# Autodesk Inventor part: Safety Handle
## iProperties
Created: 2002-02
Part Number: Safety Handle
Document SubType Name: Modeling
Designer: ***
Control State: 0
Master: False
Checked Out: False
Shininess: 77.0
Length Units: 11269
Angle Units: 11279
Time Units: 11290
Mass Units: 11283
Length Display Precision: 3
Angle Display Precision: 2
Density: 0.0
Volumn: 0.0
Area: 0.0
PropertySet Name: Model Information
Author: ***
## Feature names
1. Revolution1
2. Extrusion1
